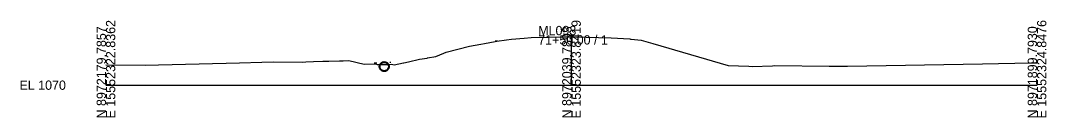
# Model space of a CAD drawing. Extents: x -26 to 14283, y -10 to 28.
# Drawn here: x 13974.3 to 14282.8, y -9.7 to 19.4 of the extents above; entities that cross this region are included whole.
import ezdxf

# ---------------------------------------------------------------- set-up
doc = ezdxf.new("R2010")
doc.units = 0
for name, color, linetype in [('3DExistingCulvert', 7, 'Continuous'), ('dsnGeopakCellCrossSection', 7, 'Continuous'), ('dsnXsExistingGround', 7, 'Continuous'), ('SurSurveyPoints', 7, 'Continuous')]:
    doc.layers.add(name, color=color, linetype=linetype)

msp = doc.modelspace()

# ---------------------------------------------------------------- linework, layer by layer
at = {"layer": '3DExistingCulvert'}
for points in [[(14082.24, 5.24), (14082.21, 5.39), (14082.2, 5.54), (14082.21, 5.7), (14082.23, 5.85), (14082.26, 6), (14082.32, 6.15), (14082.38, 6.29), (14082.46, 6.42), (14082.56, 6.54), (14082.66, 6.65), (14082.78, 6.75), (14082.91, 6.84), (14083.05, 6.92), (14083.19, 6.97), (14083.34, 7.02), (14083.49, 7.05), (14083.65, 7.06), (14083.8, 7.05), (14083.95, 7.03), (14084.1, 7), (14084.25, 6.94), (14084.39, 6.88), (14084.52, 6.8), (14084.64, 6.7), (14084.76, 6.6), (14084.86, 6.48), (14084.94, 6.35), (14085.02, 6.21), (14085.08, 6.07), (14085.12, 5.92), (14085.15, 5.77), (14085.16, 5.61), (14085.16, 5.46), (14085.13, 5.31), (14085.1, 5.16), (14085.05, 5.01), (14084.98, 4.87), (14084.9, 4.74), (14084.8, 4.62), (14084.7, 4.5), (14084.58, 4.4), (14084.45, 4.32), (14084.31, 4.24), (14084.17, 4.18), (14084.02, 4.14), (14083.87, 4.11), (14083.72, 4.1), (14083.56, 4.11), (14083.41, 4.13), (14083.26, 4.16), (14083.11, 4.21), (14082.97, 4.28), (14082.84, 4.36), (14082.72, 4.46), (14082.61, 4.56), (14082.5, 4.68), (14082.42, 4.81), (14082.34, 4.95), (14082.28, 5.09), (14082.24, 5.24)], [(14082.46, 5.29), (14082.44, 5.42), (14082.43, 5.55), (14082.43, 5.68), (14082.45, 5.81), (14082.48, 5.94), (14082.53, 6.06), (14082.58, 6.18), (14082.65, 6.29), (14082.73, 6.39), (14082.82, 6.49), (14082.92, 6.57), (14083.03, 6.65), (14083.14, 6.71), (14083.27, 6.76), (14083.39, 6.8), (14083.52, 6.82), (14083.65, 6.83), (14083.78, 6.83), (14083.91, 6.81), (14084.04, 6.78), (14084.16, 6.73), (14084.28, 6.68), (14084.39, 6.61), (14084.49, 6.53), (14084.59, 6.44), (14084.67, 6.34), (14084.75, 6.23), (14084.81, 6.11), (14084.86, 5.99), (14084.9, 5.87), (14084.92, 5.74), (14084.93, 5.61), (14084.93, 5.48), (14084.91, 5.35), (14084.88, 5.22), (14084.83, 5.1), (14084.78, 4.98), (14084.71, 4.87), (14084.63, 4.77), (14084.54, 4.67), (14084.44, 4.59), (14084.33, 4.51), (14084.22, 4.45), (14084.1, 4.4), (14083.97, 4.36), (14083.84, 4.34), (14083.71, 4.33), (14083.58, 4.33), (14083.45, 4.35), (14083.32, 4.38), (14083.2, 4.43), (14083.08, 4.48), (14082.97, 4.55), (14082.87, 4.63), (14082.77, 4.72), (14082.69, 4.82), (14082.61, 4.93), (14082.55, 5.04), (14082.5, 5.16), (14082.46, 5.29)]]:
    msp.add_lwpolyline(points, dxfattribs=at)
at = {"layer": 'dsnGeopakCellCrossSection'}
for p, q in [((14140, 0), (14140, 15)), ((14000, 0), (14140, 0)), ((14140, 0), (14280, 0))]:
    msp.add_line(p, q, dxfattribs=at)
at = {"layer": 'dsnXsExistingGround'}
msp.add_lwpolyline([(14000, 6.11), (14011.81, 6.02), (14040.17, 6.66), (14046.84, 6.87), (14050.39, 7.05), (14059.03, 6.91), (14060.1, 7.01), (14062.38, 7.12), (14065.21, 7.16), (14067.03, 7.24), (14070.26, 7.29), (14071.36, 7.31), (14073.01, 7.37), (14077.7, 6.26), (14081.1, 6.43), (14081.55, 6.24), (14083.54, 6.16), (14083.89, 6.18), (14085.09, 6.22), (14085.85, 6.32), (14086.72, 6.12), (14089.52, 6.74), (14089.57, 6.74), (14090.95, 6.98), (14094.28, 7.76), (14096.57, 8.12), (14096.68, 8.18), (14099.2, 8.65), (14101.57, 9.6), (14102.3, 9.87), (14109.3, 11.74), (14112.72, 12.33), (14113.86, 12.54), (14117.01, 13.1), (14117.54, 13.2), (14120.48, 13.61), (14121.95, 13.78), (14125.76, 14.11), (14127.89, 14.29), (14138.17, 14.49), (14140.1, 14.53), (14140.65, 14.52), (14151.9, 14.24), (14157.58, 13.87), (14157.79, 13.86), (14157.9, 13.85), (14160.98, 13.52), (14164.46, 12.51), (14187.08, 5.91), (14193.31, 5.66), (14194.38, 5.61), (14200.44, 5.84), (14201.17, 5.86), (14217.53, 5.74), (14219.49, 5.73), (14220.02, 5.72), (14220.26, 5.72), (14220.94, 5.72), (14223.05, 5.75), (14263.6, 6.37), (14278.13, 6.66), (14280, 6.7)], dxfattribs=at)
at = {"layer": 'SurSurveyPoints'}
for points in [[(14117.75, 13.18), (14117.07, 13.18)], [(14081.5, 6.57), (14080.68, 6.57)], [(14085.7, 6.77), (14085.34, 6.77)]]:
    msp.add_lwpolyline(points, dxfattribs=at)

# ---------------------------------------------------------------- texts
msp.add_text('-', height=0.0001).set_placement((14000, 0))
at = {"layer": 'dsnGeopakCellCrossSection'}
for s, p in [('E 15552322.8362', (14002.8, -10)), ('E 15552323.8419', (14142.8, -10)), ('E 15552324.8476', (14282.8, -10)), ('N 8972179.7857', (14000, -10)), ('N 8972039.7893', (14140, -10)), ('N 8971899.7930', (14280, -10))]:
    msp.add_text(s, height=2.8, rotation=90, dxfattribs=at).set_placement(p)
for s, p in [('ML093', (14130, 15)), ('71+50.00 / 1', (14130, 12.2)), ('EL 1070', (13974, -1.4))]:
    msp.add_text(s, height=2.8, dxfattribs=at).set_placement(p)

doc.saveas('drawing.dxf')
